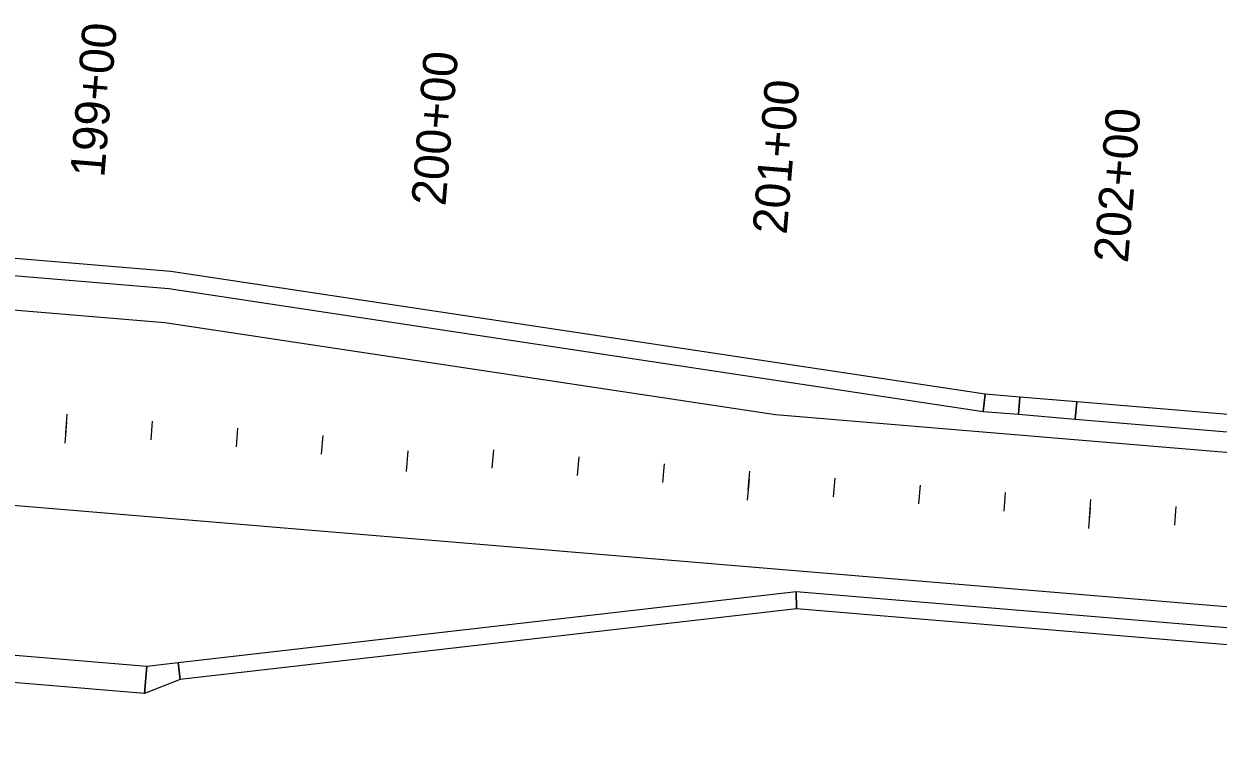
# Model space of a CAD drawing. Extents: x 20499216 to 20505321, y 7953487 to 7960535.
# Drawn here: x 20503589.5 to 20503938.3, y 7953645 to 7953855.9 of the extents above; entities that cross this region are included whole.
import ezdxf

# ---------------------------------------------------------------- set-up
doc = ezdxf.new("R2010")
doc.units = 0
for name, color, linetype in [('EXT_CU', 7, 'Continuous'), ('EXT_RR', 7, 'Continuous'), ('NamedBoundary', 7, 'Continuous'), ('Safety', 7, 'Continuous')]:
    doc.layers.add(name, color=color, linetype=linetype)

msp = doc.modelspace()

# ---------------------------------------------------------------- linework, layer by layer
at = {"layer": 'EXT_CU'}
for points in [[(20503631.86, 7953778.64), (20503869.7, 7953742.74), (20503870.28, 7953747.71), (20503632.44, 7953783.61), (20503288.69, 7953812.3), (20503288.28, 7953807.31)], [(20503870.28, 7953747.71), (20503869.7, 7953742.74), (20503880, 7953741.88), (20503880.41, 7953746.87)], [(20503880.41, 7953746.87), (20503880, 7953741.88), (20503896.61, 7953740.5), (20503897.02, 7953745.48)], [(20503897.02, 7953745.48), (20503896.61, 7953740.5), (20504251.88, 7953710.85), (20504251.8, 7953715.88)], [(20503624.75, 7953660.41), (20503373.07, 7953681.37), (20503373.73, 7953689.35), (20503625.39, 7953668.38)], [(20503815.08, 7953690.11), (20503815.16, 7953685.08), (20503635.14, 7953664.47), (20503634.57, 7953669.44)], [(20504246.23, 7953649.11), (20503815.16, 7953685.08), (20503815.08, 7953690.11), (20504247.14, 7953654.05)], [(20503625.39, 7953668.38), (20503634.57, 7953669.44), (20503635.14, 7953664.47), (20503624.75, 7953660.41)]]:
    msp.add_lwpolyline(points, close=True, dxfattribs=at)
at = {"layer": 'EXT_RR'}
for p, q in [((20503602.01, 7953739.56), (20503601.51, 7953733.46)), ((20503626.67, 7953734.43), (20503627.13, 7953739.87)), ((20503651.59, 7953732.35), (20503652.04, 7953737.79)), ((20503676.5, 7953730.27), (20503676.95, 7953735.71)), ((20503701.67, 7953731.24), (20503701.16, 7953725.14)), ((20503726.33, 7953726.11), (20503726.78, 7953731.55)), ((20503751.24, 7953724.03), (20503751.69, 7953729.47)), ((20503776.15, 7953721.95), (20503776.61, 7953727.39)), ((20503801.32, 7953722.92), (20503800.81, 7953716.82)), ((20503825.98, 7953717.79), (20503826.43, 7953723.24)), ((20503850.89, 7953715.72), (20503851.35, 7953721.16)), ((20503875.81, 7953713.64), (20503876.26, 7953719.08)), ((20503900.97, 7953714.61), (20503900.47, 7953708.51)), ((20503925.63, 7953709.48), (20503926.09, 7953714.92))]:
    msp.add_line(p, q, dxfattribs=at)
at = {"layer": 'NamedBoundary'}
for points in [[(20503281.84, 7953797.82), (20503630.7, 7953768.71), (20503809.08, 7953741.78), (20504366.9, 7953695.23), (20504431.47, 7953689.85)], [(20504427.73, 7953645), (20504246.09, 7953660.16), (20503289.01, 7953740.03), (20503289.01, 7953740.03)]]:
    msp.add_lwpolyline(points, dxfattribs=at)
at = {"layer": 'Safety'}
for p, q in [((20503601.76, 7953736.51), (20503602.21, 7953741.95)), ((20503701.67, 7953731.24), (20503701.16, 7953725.14)), ((20503801.07, 7953719.87), (20503801.52, 7953725.31)), ((20503900.72, 7953711.56), (20503901.17, 7953717))]:
    msp.add_line(p, q, dxfattribs=at)

# ---------------------------------------------------------------- texts
at = {"layer": 'EXT_RR'}
for s, p in [('199+00', (20503612.99, 7953810.83)), ('200+00', (20503712.64, 7953802.51)), ('201+00', (20503812.3, 7953794.2)), ('202+00', (20503911.95, 7953785.88))]:
    msp.add_text(s, height=10.02, rotation=85.2296, dxfattribs=at).set_placement(p)
at = {"layer": 'Safety'}
msp.add_text('200+00', height=10.02, rotation=85.2296, dxfattribs=at).set_placement((20503712.64, 7953802.51))

doc.saveas('drawing.dxf')
